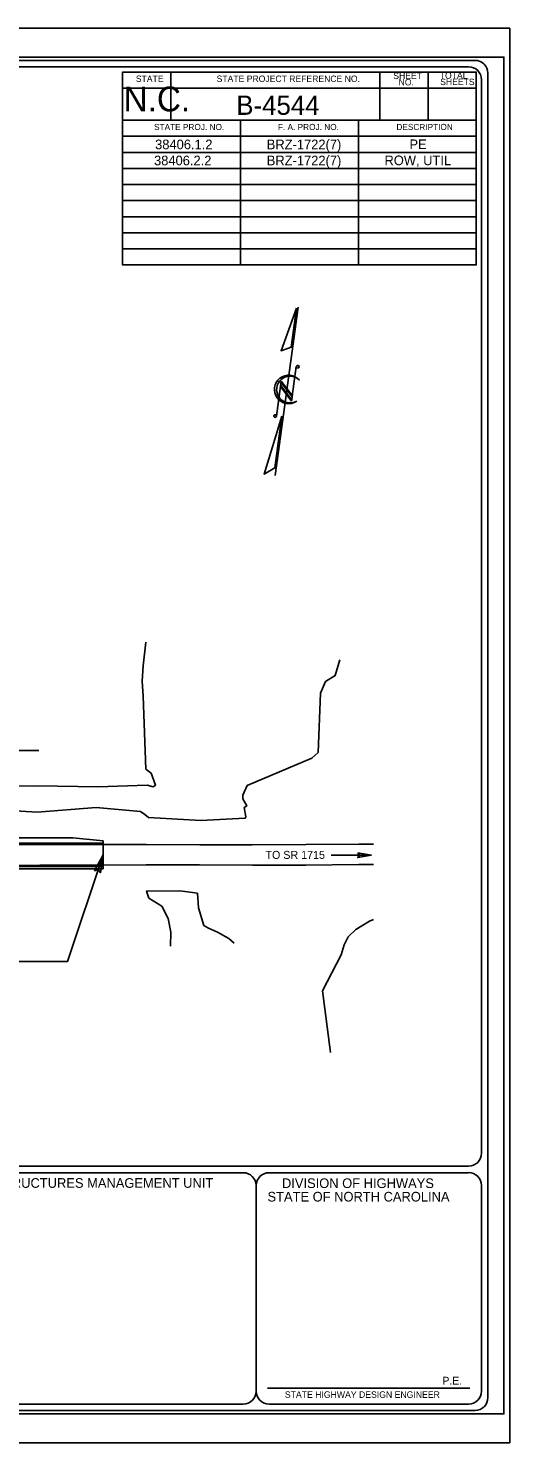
# Model space of a CAD drawing. Extents: x 0 to 2021, y 0 to 1321.
# Drawn here: x 1572 to 2021, y 0 to 1321 of the extents above; entities that cross this region are included whole.
import ezdxf

# ---------------------------------------------------------------- set-up
doc = ezdxf.new("R2010")
doc.units = 0
for name, color, linetype in [('Default', 7, 'Continuous'), ('Dimension Lines', 7, 'Continuous'), ('Exist Hydro Stream or Body of Water', 7, 'Continuous'), ('Exist Roads EOP', 7, 'Continuous'), ('Prop EOT', 7, 'Continuous'), ('Sheet Data Field CELL', 7, 'Continuous'), ('Sheet North Arrow CELL', 7, 'Continuous'), ('Sheet Plot Border Inside CELL', 7, 'Continuous'), ('Sheet Plot Border Outside CELL', 7, 'Continuous'), ('Sheet Title CELL', 7, 'Continuous'), ('Text', 7, 'Continuous')]:
    doc.layers.add(name, color=color, linetype=linetype)

msp = doc.modelspace()

# ---------------------------------------------------------------- linework, layer by layer
at = {"layer": 'Default'}
for p, q in [((1502.9, 564.9), (1613.5, 564.9)), ((1502.9, 564.9), (1613.5, 564.9)), ((1613.5, 564.9), (1641.6, 561.9)), ((1613.5, 564.9), (1641.6, 561.9)), ((1641.6, 561.9), (1641.6, 535.9)), ((1641.6, 561.9), (1641.6, 559.9)), ((1892, 548.6), (1854.6, 548.6)), ((1641.6, 535.9), (1559.9, 535.9)), ((1559.9, 535.9), (1641.6, 535.9)), ((1641.6, 537.9), (1641.6, 535.9))]:
    msp.add_line(p, q, dxfattribs=at)
for points in [[(1633.7, 534.1), (1641.6, 548.9), (1639.2, 532.2), (1637, 535.1)], [(1879.4, 550.8), (1892, 548.6), (1879.3, 546.4), (1880.9, 548.6)]]:
    msp.add_lwpolyline(points, close=True, dxfattribs=at)
at = {"layer": 'Dimension Lines'}
for p, q in [((1498.9, 646.3), (1581.8, 646.3)), ((1641.6, 548.9), (1608.3, 449.3)), ((1608.3, 449.3), (1343, 449.3))]:
    msp.add_line(p, q, dxfattribs=at)
at = {"layer": 'Exist Hydro Stream or Body of Water'}
for points in [[(1681.6, 628.9), (1679, 697), (1678, 710.9), (1678.9, 725.5), (1681.4, 747.5)], [(1842.3, 644.3), (1844.6, 699.8), (1849.3, 710.7), (1858.4, 716.2), (1862.6, 731)], [(1429, 567.6), (1432.9, 575), (1436, 578.9), (1440.9, 581.2), (1449.4, 584.6), (1484.6, 586.2), (1533.6, 591.4), (1580.2, 588.6), (1635.2, 593.2), (1676.5, 589.5), (1680.5, 586.7), (1684, 583.8), (1733, 580.8), (1774.3, 583), (1774.8, 584.4), (1773.2, 593), (1775.8, 594.6), (1772.2, 601.2), (1772.2, 604.6), (1776.1, 613.6), (1836.6, 639), (1842.3, 644.3)], [(1636.7, 612.3), (1580.5, 613.2), (1532.6, 613), (1488.7, 616.1), (1444.2, 609.6), (1438.9, 610.9), (1437.9, 613.4), (1439, 617.7), (1441.7, 622.4), (1447.6, 630.2), (1453.7, 634.4), (1456.1, 639.7)], [(1636.7, 612.3), (1682.7, 614), (1688.4, 612.4), (1690.6, 614), (1686.4, 625), (1681.6, 628.9)], [(1704.7, 463.6), (1704.8, 476.8), (1702.3, 489.6), (1696.4, 500.9), (1684.3, 508.5), (1682.3, 515.1), (1713.4, 515.3), (1729.7, 513), (1730.6, 499.3), (1735.6, 483), (1740.1, 480.5), (1748.5, 476.6), (1759.1, 470.7), (1764, 466.4)], [(1863.7, 455.6), (1866.6, 464.9), (1870.5, 472.4), (1877.6, 479.2), (1890.3, 487.1), (1894, 488.4)], [(1863.7, 455.6), (1846.3, 421.9), (1853.8, 364.4)]]:
    msp.add_lwpolyline(points, dxfattribs=at)
at = {"layer": 'Exist Roads EOP'}
for points in [[(1432.3, 549), (1432.3, 558.5), (1483.3, 558.8), (1532.5, 558.6), (1582.3, 558.5), (1632.3, 558.5), (1681.9, 558.6), (1731.9, 558.3), (1780.9, 558.3), (1831, 558.5), (1880.4, 558.8), (1894, 558.8)], [(1432.3, 549), (1432.2, 539.3), (1483, 539.2), (1532.5, 539), (1582.6, 539.1), (1632.1, 539.3), (1681.7, 539.5), (1731.7, 539.5), (1781.1, 539.4), (1830.8, 539.3), (1880.3, 539.8), (1894, 539.9)]]:
    msp.add_lwpolyline(points, dxfattribs=at)
at = {"layer": 'Prop EOT'}
for p, q in [((751.5, 559.9), (1641.6, 559.9)), ((1641.6, 559.9), (1641.6, 537.9)), ((751.5, 537.9), (1641.6, 537.9))]:
    msp.add_line(p, q, dxfattribs=at)
at = {"layer": 'Sheet North Arrow CELL'}
for p, q in [((1802.1, 903), (1823.6, 1060.4)), ((1822, 1004.8), (1817.6, 972.5)), ((1807.9, 991.2), (1803.5, 958.4)), ((1818.3, 977.5), (1807.9, 991.2)), ((1824.9, 992.2), (1825, 992)), ((1817.6, 972.5), (1807.2, 986.2)), ((1807.8, 990), (1807.4, 987.1)), ((1817.8, 973.4), (1807.4, 987.1)), ((1807.4, 987.1), (1817.8, 973.4)), ((1818.2, 976.4), (1807.8, 990)), ((1817.8, 973.4), (1818.2, 976.4))]:
    msp.add_line(p, q, dxfattribs=at)
for points in [[(1822.3, 1059.2), (1807.7, 1019.5), (1817.3, 1022.8)], [(1808.4, 958.6), (1791.9, 904.4), (1801.8, 910.2)]]:
    msp.add_lwpolyline(points, close=True, dxfattribs=at)
for centre in [(1823.3, 1004.6), (1802.2, 958.5)]:
    msp.add_ellipse(centre, major_axis=(-0.28, 1.27), ratio=0.999692, dxfattribs=at)
for centre, major_axis, start_param, end_param in [((1814.8, 983.4), (2.8, -13), 2.056008, 6.673347), ((1816.1, 983.3), (2.7, -12.2), 2.147726, 6.60763)]:
    msp.add_ellipse(centre, major_axis=major_axis, ratio=0.999692, start_param=start_param, end_param=end_param, dxfattribs=at)
at = {"layer": 'Sheet Plot Border Inside CELL'}
msp.add_lwpolyline([(15.6, 26.9), (2015.8, 26.9), (2015.8, 1293.7), (15.6, 1293.7)], close=True, dxfattribs=at)
at = {"layer": 'Sheet Plot Border Outside CELL'}
msp.add_lwpolyline([(2021.2, 1320.6), (0, 1320.6), (0, 0), (2021.2, 0)], close=True, dxfattribs=at)
at = {"layer": 'Sheet Title CELL'}
for p, q in [((278.5, 258.1), (1982.8, 258.1)), ((1532.7, 252.1), (1772.4, 252.1)), ((1796.5, 252.1), (1982.8, 252.1)), ((1784.4, 48), (1784.4, 240.1)), ((1795.1, 51), (1984, 51))]:
    msp.add_line(p, q, dxfattribs=at)
for points in [[(1988.8, 1290.6), (212.4, 1290.6)], [(1982.8, 1284.6), (278.5, 1284.6)], [(1659.9, 1099.7), (1990, 1099.7), (1990, 1114.7), (1659.9, 1114.7), (1659.9, 1129.7), (1990, 1129.7), (1990, 1144.7), (1659.9, 1144.7), (1659.9, 1159.8), (1990, 1159.8), (1990, 1174.8), (1659.9, 1174.8), (1659.9, 1189.8), (1990, 1189.8), (1990, 1204.8), (1659.9, 1204.8), (1659.9, 1219.8), (1990, 1219.8), (1990, 1234.8), (1659.9, 1234.8), (1659.9, 1264.8), (1990, 1264.8), (1990, 1279.8), (1659.9, 1279.8), (1659.9, 1099.7), (1769.9, 1099.7), (1769.9, 1234.8), (1704.9, 1234.8), (1704.9, 1279.8), (1900, 1279.8), (1899.9, 1234.8), (1879.9, 1234.8), (1879.9, 1099.7), (1990, 1099.7), (1990, 1279.8), (1945, 1279.8), (1945, 1234.8)], [(1994.8, 270.1), (1994.8, 1272.6)], [(2000.8, 42), (2000.8, 1278.6)], [(1994.8, 48), (1994.8, 240.1)], [(212.4, 30), (1988.8, 30)], [(1532.7, 36), (1772.5, 36)], [(1796.5, 36), (1982.8, 36)]]:
    msp.add_lwpolyline(points, dxfattribs=at)
for centre, major_axis, start_param, end_param in [((1982.8, 1272.7), (0, 12), 4.712389, 6.283185), ((1988.8, 1278.7), (0, 12), 4.712389, 6.283185), ((1982.8, 270.2), (0, 12), 3.141593, 4.712389), ((1772.4, 240.1), (0, 12), 4.712389, 6.283185), ((1796.5, 240.1), (0, 12), 0, 1.570796), ((1982.8, 240.2), (0, 12), 4.712389, 6.283185), ((1772.5, 48.1), (0, 12), 3.141593, 4.712389), ((1796.5, 48.1), (0, -12), 4.712389, 6.283185), ((1982.8, 48.1), (0, -12), 0, 1.570796), ((1988.8, 42.1), (0, -12), 0, 1.570796)]:
    msp.add_ellipse(centre, major_axis=major_axis, ratio=0.999692, start_param=start_param, end_param=end_param, dxfattribs=at)

# ---------------------------------------------------------------- texts
at = {"layer": 'Dimension Lines'}
msp.add_text('P.E.', height=7.26, dxfattribs=at).set_placement((1958.4, 54.3))
at = {"layer": 'Sheet Data Field CELL'}
for s, height, p in [('B-4544', 18.01, (1766, 1239.8)), ('PE', 9, (1927.6, 1207.8)), ('ROW, UTIL', 9, (1904.3, 1192.8))]:
    msp.add_text(s, height=height, dxfattribs=at).set_placement(p)
for s, height, p in [('38406.1.2', 9, (1690.2, 1207.7)), ('BRZ-1722(7)', 9.004, (1794.4, 1207.7)), ('38406.2.2', 9, (1689.2, 1192.7)), ('BRZ-1722(7)', 9.004, (1794.4, 1192.7))]:
    msp.add_text(s, height=height, rotation=360, dxfattribs=at).set_placement(p)
at = {"layer": 'Sheet Title CELL'}
for s, height, p in [('STATE', 6, (1672.2, 1270.5)), ('STATE PROJECT REFERENCE NO.', 6.003, (1747.6, 1270.5)), ('SHEET', 6, (1912.5, 1273.2)), ('NO.', 6, (1917.5, 1267.3)), ('TOTAL', 6, (1955.9, 1273.6)), ('SHEETS', 6, (1956.3, 1267.6)), ('N.C.', 23.23, (1660.8, 1243)), ('STATE PROJ. NO.', 5.763, (1689.2, 1225.6)), ('F. A. PROJ. NO.', 5.763, (1804.8, 1225.6)), ('DESCRIPTION', 5.763, (1915.4, 1225.6)), ('STRUCTURES MANAGEMENT UNIT', 9.004, (1541.1, 238)), ('DIVISION OF HIGHWAYS', 9.004, (1808.6, 237.8)), ('STATE OF NORTH CAROLINA', 9.004, (1795.1, 225.2))]:
    msp.add_text(s, height=height, dxfattribs=at).set_placement(p)
msp.add_text('STATE HIGHWAY DESIGN ENGINEER', height=6.048, rotation=360, dxfattribs=at).set_placement((1811.3, 41.9))
at = {"layer": 'Text'}
msp.add_text('TO SR 1715', height=7.47, dxfattribs=at).set_placement((1793.2, 545.1))

doc.saveas('drawing.dxf')
